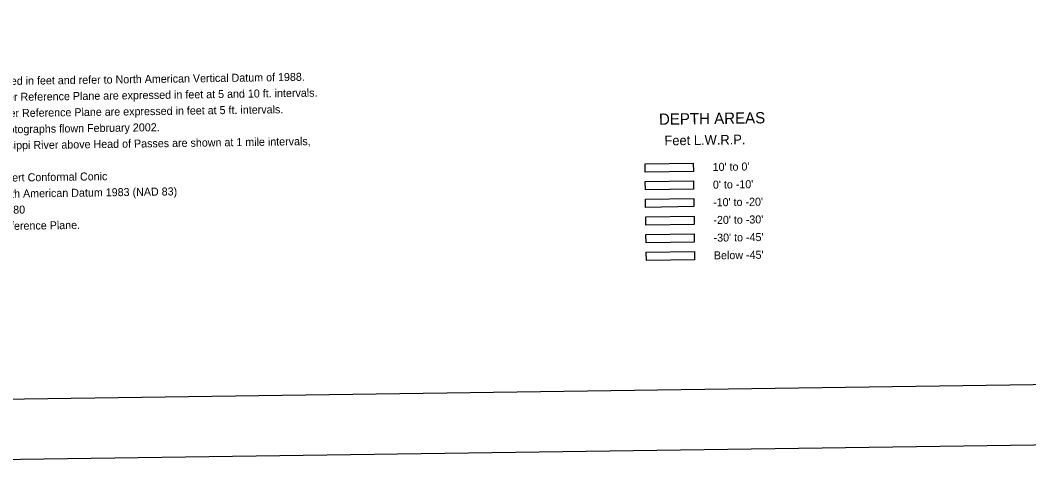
# Model space of a CAD drawing. Extents: x 3775218 to 3813389, y 343470 to 369318.
# Drawn here: x 3781032 to 3791487, y 344054 to 348666 of the extents above; entities that cross this region are included whole.
import ezdxf

# ---------------------------------------------------------------- set-up
doc = ezdxf.new("R2010")
doc.units = 0
for name, color, linetype in [('G-ANNO-NPLT', 7, 'Continuous'), ('V-ANNO-NOTE', 7, 'Continuous'), ('V-ANNO-SYMB', 7, 'Continuous'), ('V-TOPO-DPTH', 7, 'Continuous')]:
    doc.layers.add(name, color=color, linetype=linetype)

msp = doc.modelspace()

# ---------------------------------------------------------------- linework, layer by layer
at = {"layer": 'G-ANNO-NPLT'}
msp.add_lwpolyline([(3776142, 344054), (3812805, 344571), (3812464, 368735), (3775801, 368218)], close=True, dxfattribs=at)
at = {"layer": 'V-ANNO-SYMB'}
msp.add_lwpolyline([(3778883, 344717), (3811963, 345184), (3811640, 368098), (3778560, 367632), (3778883, 344717)], dxfattribs=at)
at = {"layer": 'V-TOPO-DPTH'}
for points in [[(3787509, 347179), (3788009, 347186), (3788010, 347101), (3787510, 347094)], [(3787511, 346996), (3788011, 347003), (3788013, 346918), (3787513, 346911)], [(3787514, 346813), (3788014, 346820), (3788015, 346736), (3787515, 346728)], [(3787517, 346630), (3788017, 346638), (3788018, 346553), (3787518, 346545)], [(3787519, 346447), (3788019, 346455), (3788020, 346370), (3787520, 346362)], [(3787522, 346264), (3788022, 346272), (3788023, 346187), (3787523, 346180)]]:
    msp.add_lwpolyline(points, close=True, dxfattribs=at)

# ---------------------------------------------------------------- texts
at = {"layer": 'V-ANNO-NOTE'}
for s, rotation, p in [('All elevations are expressed in feet and refer to North American Vertical Datum of 1988.', 0.8084, (3779671, 347978)), ('Contours below Low Water Reference Plane are expressed in feet at 5 and 10 ft. intervals.', 0.8084, (3779673, 347812)), ('Contours above Low Water Reference Plane are expressed in feet at 5 ft. intervals.', 0.8084, (3779676, 347645)), ('Planimetry from aerial photographs flown February 2002.', 0.8084, (3779678, 347478)), ('Distances on Mississippi River above Head of Passes are shown at 1 mile intervals,', 0.8084, (3779930, 347315)), ('Projection .............. Lambert Conformal Conic', 0.8083, (3779685, 346978)), ('Horizontal Datum ..... North American Datum 1983 (NAD 83)', 0.8083, (3779687, 346811)), ('Ellipsoid ................. GRS 80', 0.8083, (3779690, 346645)), ('L.W.R.P. - Low Water Reference Plane.', 0.8083, (3779692, 346478))]:
    msp.add_text(s, height=83, rotation=rotation, dxfattribs=at).set_placement(p)
at = {"layer": 'V-TOPO-DPTH'}
for s, height, p in [('DEPTH AREAS', 116.7, (3787654, 347583)), ('Feet L.W.R.P.', 100, (3787711, 347370)), ("10' to 0'", 83, (3788210, 347105)), ("0' to -10'", 83, (3788213, 346922)), ("-10' to -20'", 83, (3788215, 346739)), ("-20' to -30'", 83, (3788218, 346556)), ("-30' to -45'", 83, (3788220, 346373)), ("Below -45'", 83, (3788223, 346190))]:
    msp.add_text(s, height=height, rotation=0.8084, dxfattribs=at).set_placement(p)

doc.saveas('drawing.dxf')
